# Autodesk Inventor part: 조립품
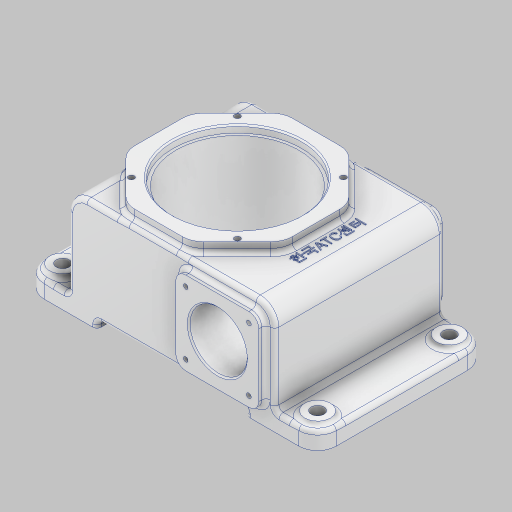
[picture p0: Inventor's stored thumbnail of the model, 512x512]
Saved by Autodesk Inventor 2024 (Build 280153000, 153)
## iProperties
Created: 2026-02
Part Number: 조립품
Material: 알루미늄 6061
Document SubType Name: Modeling
Designer: 2-10
Density: 2.7 g/cm^3
Appearance: 알루미늄 - 평지
Mass: 2338.38 g
Surface Area: 1210.62 cm^2
Volume: 866.066 cm^3
Author: 2-10
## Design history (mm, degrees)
sketch "스케치1"
  geometry: L1 (-72, -35)-(72, -35); L2 (72, -35)-(72, 35); L3 (72, 35)-(-72, 35); L4 (-72, 35)-(-72, -35); L5 (-72, -35)-(72, 35); L6 (72, -35)-(-72, 35); L7 (-102, -28)-(-52, -28); L8 (-52, -28)-(-52, -40); L9 (-52, -40)-(-102, -40); L10 (-102, -40)-(-102, -28); L11 (-102, -28)-(-52, -40); L12 (-52, -28)-(-102, -40); L13 (52, -28)-(102, -28); L14 (102, -28)-(102, -40); L15 (102, -40)-(52, -40); L16 (52, -40)-(52, -28); L17 (52, -28)-(102, -40); L18 (102, -28)-(52, -40); 6 further points
  constraints: 36 end point, 8 midpoint, 6 parallel, 3 horizontal, 3 perpendicular, 2 equal length, 1 coincident
  dimensions: "d0" = 144 distance of L3.end L2.end; "d1" = 70 distance of L2.end L1.end; "d3" = 50 distance between parallel lines of L8 L10; "d6" = 204 distance between parallel lines of L14 L10; "d7" = 30 distance between parallel lines of L14 L2; "d42" = 5 distance between parallel lines of L1 L15; "d43" = 12 distance between parallel lines of L13 L15; "d44" = 5 distance between parallel lines of L1 L9
extrude "돌출1" new body sketch "스케치1" stored distance "d8" = 118; taper "d9" = 0 deg
extrude "돌출2" join sketch "스케치1" stored distance "d10" = 118; taper "d11" = 0 deg
sketch "스케치2"
  geometry: L1 (52, -40)-(102, -40) reference; L2 (102, -28)-(72, -28) reference; L3 (15, -29)-(59, -29); L4 (66, -22)-(66, 22); L5 (59, 29)-(15, 29); L6 (8, 22)-(8, -22); L7 (8, -29)-(66, 29); L8 (66, -29)-(8, 29); L9 (102, -40)-(102, -28) reference; A1 r 7 centre (15, 22) between (15, 29) and (8, 22); A2 r 7 centre (15, -22) between (8, -22) and (15, -29); A3 r 7 centre (59, -22) between (59, -29) and (66, -22); A4 r 7 centre (59, 22) between (66, 22) and (59, 29); 4 further points
  constraints: 12 end point, 8 point on circle, 8 point on line, 8 tangent, 4 centre point, 4 midpoint, 3 equal radius, 2 parallel, 1 horizontal, 1 perpendicular
  dimensions: "d12" = 58 distance of L8.end L7.end; "d13" = 58 distance of L7.end L8.start; "d14" = 40 distance from line of point (37, 0) L1; "d16" = 7 radius of A1; "d137" = 65 distance from line of point (37, 29) L9
extrude "돌출3" join sketch "스케치2" distance "d17" = 5; taper "d18" = 0 deg
sketch "스케치3"
  geometry: L1 (8.393, 86.175)-(31.825, 109.607); L2 (42.431, 114)-(75.569, 114); L3 (86.175, 109.607)-(109.607, 86.175); L4 (114, 75.569)-(114, 42.431); L5 (109.607, 31.825)-(86.175, 8.393); L6 (75.569, 4)-(42.431, 4); L7 (31.825, 8.393)-(8.393, 31.825); L8 (4, 42.431)-(4, 75.569); L9 (131, 123)-(87, 123) reference; L10 (131, -5)-(87, -5) reference; L11 (-30, 118)-(-30, 0) reference; A1 r 15 centre (42.431, 19) between (31.825, 8.393) and (42.431, 4); A2 r 15 centre (19, 42.431) between (4, 42.431) and (8.393, 31.825); A3 r 15 centre (19, 75.569) between (8.393, 86.175) and (4, 75.569); A4 r 15 centre (42.431, 99) between (42.431, 114) and (31.825, 109.607); A5 r 15 centre (75.569, 99) between (86.175, 109.607) and (75.569, 114); A6 r 15 centre (99, 75.569) between (114, 75.569) and (109.607, 86.175); A7 r 15 centre (99, 42.431) between (109.607, 31.825) and (114, 42.431); A8 r 15 centre (75.569, 19) between (75.569, 4) and (86.175, 8.393); 13 further points
  constraints: 16 end point, 16 point on circle, 16 point on line, 16 tangent, 8 centre point, 7 equal radius, 4 midpoint, 1 horizontal alignment, 1 vertical, 17 other
  dimensions: "d31" = 15 radius of A1; "d138" = 50 horizontal distance of point (59, 59) point (109, -5); "d139" = 33.13708 distance of L2.start L2.end
extrude "돌출4" join sketch "스케치3" distance "d32" = 7; taper "d33" = 0 deg
sketch "스케치4"
  geometry: L1 (59, 29)-(15, 29) reference; L2 (15, -29)-(59, -29) reference; L3 (8, 22)-(8, -22) reference; L4 (59, 29)-(15, 29) reference; L5 (66, -22)-(66, 22) reference; L6 (-13, 76.49)-(-13, -76.49); L7 (-63.607, 42)-(-40.175, 42) reference; L8 (-29.569, 42)-(-40.175, 42) reference; L9 (-29.569, 42)-(3.569, 42) reference; L10 (14.175, 42)-(3.569, 42) reference; L11 (14.175, 42)-(37.607, 42) reference; L12 (42, 42)-(37.607, 42) reference; L13 (-63.607, 42)-(-68, 42) reference; L14 (-58, 42)-(-58, 37); L15 (-58, 37)-(-56, 37); L16 (-56, 37)-(-56, -24); L17 (-56, -24)-(-13, -24); A1 r 7 centre (59, -22) between (59, -29) and (66, -22) reference; A2 r 7 centre (15, -22) between (8, -22) and (15, -29) reference; A3 r 7 centre (15, 22) between (15, 29) and (8, 22) reference; A4 r 7 centre (59, 22) between (66, 22) and (59, 29) reference; 5 further points
  constraints: 10 end point, 3 perpendicular, 2 midpoint, 2 point on line, 2 vertical, 1 horizontal alignment
  dimensions: "d34" = 50 distance from line of L6 point (37, -29); "d35" = 90 diameter of L14 L6; "d36" = 86 diameter of L16 L6; "d37" = 5 distance between parallel lines of L15 L7; "d38" = 66 distance between parallel lines of L17 L7
revolve "회전1" sketch "스케치4" stored, may be unused: angle "d45" = 90 deg
sketch "스케치5"
  geometry: L1 (30, -24)-(-56, -24) reference; L2 (-13, 15.405)-(-13, -63.405); L3 (-58, 42)-(32, 42) reference; L4 (-13, -18)-(12, -18); L5 (12, -18)-(18, -24); 2 further points
  constraints: 6 end point, 2 midpoint, 2 point on line, 1 horizontal, 1 vertical
  dimensions: "d48" = 6 distance between parallel lines of L4 L1; "d49" = 45 deg angle of L2 L5; "d50" = 50 diameter of L4.end L2
revolve "회전2" sketch "스케치5" stored, may be unused: angle "d51" = 90 deg
sketch "스케치6"
  geometry: L1 (-13, 36)-(-13, -72); L2 (-38, -18)-(12, -18) reference; L3 (-33, -18)-(-33, -27.5); L4 (-31.5, -29)-(-13, -29); A1 r 1.5 centre (-31.5, -27.5) between (-33, -27.5) and (-31.5, -29); 3 further points
  constraints: 6 end point, 4 point on line, 2 midpoint, 2 point on circle, 2 tangent, 2 vertical, 1 centre point, 1 perpendicular
  dimensions: "d52" = 40 diameter of L3 L1; "d53" = 11 distance between parallel lines of L2 L4; "d55" = 1.5 radius of A1
revolve "회전3" sketch "스케치6" stored, may be unused: angle "d54" = 90 deg
sketch "스케치7"
  geometry: L1 (59, 29)-(15, 29) reference; L2 (8, 22)-(8, -22) reference; C1 r 20 at (37, 0); 3 further points
  constraints: 2 midpoint, 1 centre point, 1 horizontal alignment, 1 vertical alignment
  dimensions: "d56" = 40 diameter of C1
extrude "돌출5" cut sketch "스케치7" extent not by distance; stored distance "d57" = 0; taper "d58" = 0 deg
fillet "모깎기19" dims "d135" = 13
fillet "모깎기1" dims "d59" = 13
fillet "모깎기3" dims "d61" = 3
sketch "스케치10"
  geometry: L1 (0, 7)-(44, 7); L2 (44, 7)-(44, 51); L3 (44, 51)-(0, 51); L4 (0, 51)-(0, 7); L5 (0, 7)-(44, 51); L6 (44, 7)-(0, 51); C1 r 20 at (22, 29) reference; 5 further points
  constraints: 12 end point, 4 coincident, 2 midpoint, 2 parallel, 1 horizontal, 1 perpendicular
  dimensions: "d88" = 44 distance of L3.end L2.end; "d89" = 44 distance of L2.end L1.end
hole "구멍2" sketch "스케치10" at (0, 51), (44, 51), (0, 7), (44, 7) diameter "d81" = 3.242; stored, may be unused: countersink angle "d85" = 90 deg, drill point angle "d87" = 118 deg; dims "d82" = 8, "d83" = 4, "d84" = 2, "d86" = 10
sketch "스케치11"
  geometry: L1 (96, 22)-(22, 22); L2 (22, 22)-(22, 96); L3 (22, 96)-(96, 96); L4 (96, 96)-(96, 22); L5 (96, 22)-(22, 96); L6 (22, 22)-(96, 96); C1 r 45 at (59, 59) reference; 5 further points
  constraints: 12 end point, 4 coincident, 2 midpoint, 2 parallel, 1 horizontal, 1 perpendicular
  dimensions: "d97" = 74 distance of L2.end L3.end; "d98" = 74 distance of L1.end L2.end
hole "구멍3" sketch "스케치11" at (22, 22), (22, 96), (96, 22), (96, 96) diameter "d90" = 4.134; stored, may be unused: countersink angle "d94" = 90 deg, drill point angle "d96" = 118 deg; dims "d91" = 10, "d92" = 4, "d93" = 2, "d95" = 12
sketch "스케치12"
  geometry: C1 r 9 at (13, 92); C2 r 9 at (13, 0); C3 r 9 at (191, 92); C4 r 9 at (191, 0); A1 r 13 centre (13, 92) between (13, 105) and (0, 92) reference; A2 r 13 centre (13, 0) between (0, 0) and (13, -13) reference; A3 r 13 centre (191, 92) between (204, 92) and (191, 105) reference; A4 r 13 centre (191, 0) between (191, -13) and (204, 0) reference; 1 further point
  constraints: 4 centre point, 4 concentric
  dimensions: "d99" = 18 diameter of C1; "d100" = 18 diameter of C2; "d101" = 18 diameter of C4; "d102" = 18 diameter of C3
extrude "돌출7" join sketch "스케치12" distance "d103" = 3; taper "d104" = 0 deg
fillet "모깎기5" dims "d105" = 3
fillet "모깎기7" dims "d107" = 3
fillet "모깎기8" dims "d108" = 3
fillet "모깎기11" dims "d111" = 3
chamfer "모따기1" distance "d114" = 1; stored, may be unused: second distance "d115" = 2, angle "d116" = 45 deg
fillet "모깎기14" dims "d117" = 3
chamfer "모따기2" distance "d118" = 1; stored, may be unused: second distance "d119" = 2, angle "d120" = 45 deg
sketch "스케치13"
  geometry: C1 r 9 at (0, 0) reference; C2 r 9 at (0, 92) reference; C3 r 9 at (-178, 0) reference; C4 r 9 at (-178, 92) reference; 5 further points
  constraints: 4 coincident
hole "구멍4" sketch "스케치13" at (0, 0), (0, 92), (-178, 0), (-178, 92) diameter "d121" = 9; stored, may be unused: countersink angle "d125" = 90 deg, drill point angle "d127" = 0 deg; dims "d122" = 10, "d123" = 4, "d124" = 2, "d126" = 12
node "작업 평면3"
sketch "스케치14"
  geometry: C1 r 18.5 at (-58, 16.569) reference; 2 further points
  constraints: 1 horizontal alignment, 1 other
  dimensions: "d128" = 65 distance of C1.centre point (7, 16.569)
feature "엠보싱1" dims "d0" = 144, "d1" = 70, "d3" = 50, "d6" = 204, "d7" = 30, "d42" = 5, "d43" = 12, "d44" = 5, "d132" = 0.5, "d133" = 0
fillet "모깎기20" dims "d136" = 3
fillet "모깎기21" dims "d140" = 3
node "솔리드1"
mirror "미러1"
mirror "미러2"
node "투영된 루프1"
feature "A9D066F2-1C7D-4E18-AEED-F7BC21143FA4" dims "d81" = 3.242, "d82" = 8, "d83" = 4, "d84" = 2, "d85" = 90 deg, "d86" = 10, "d87" = 118 deg
